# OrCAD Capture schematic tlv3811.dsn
size A
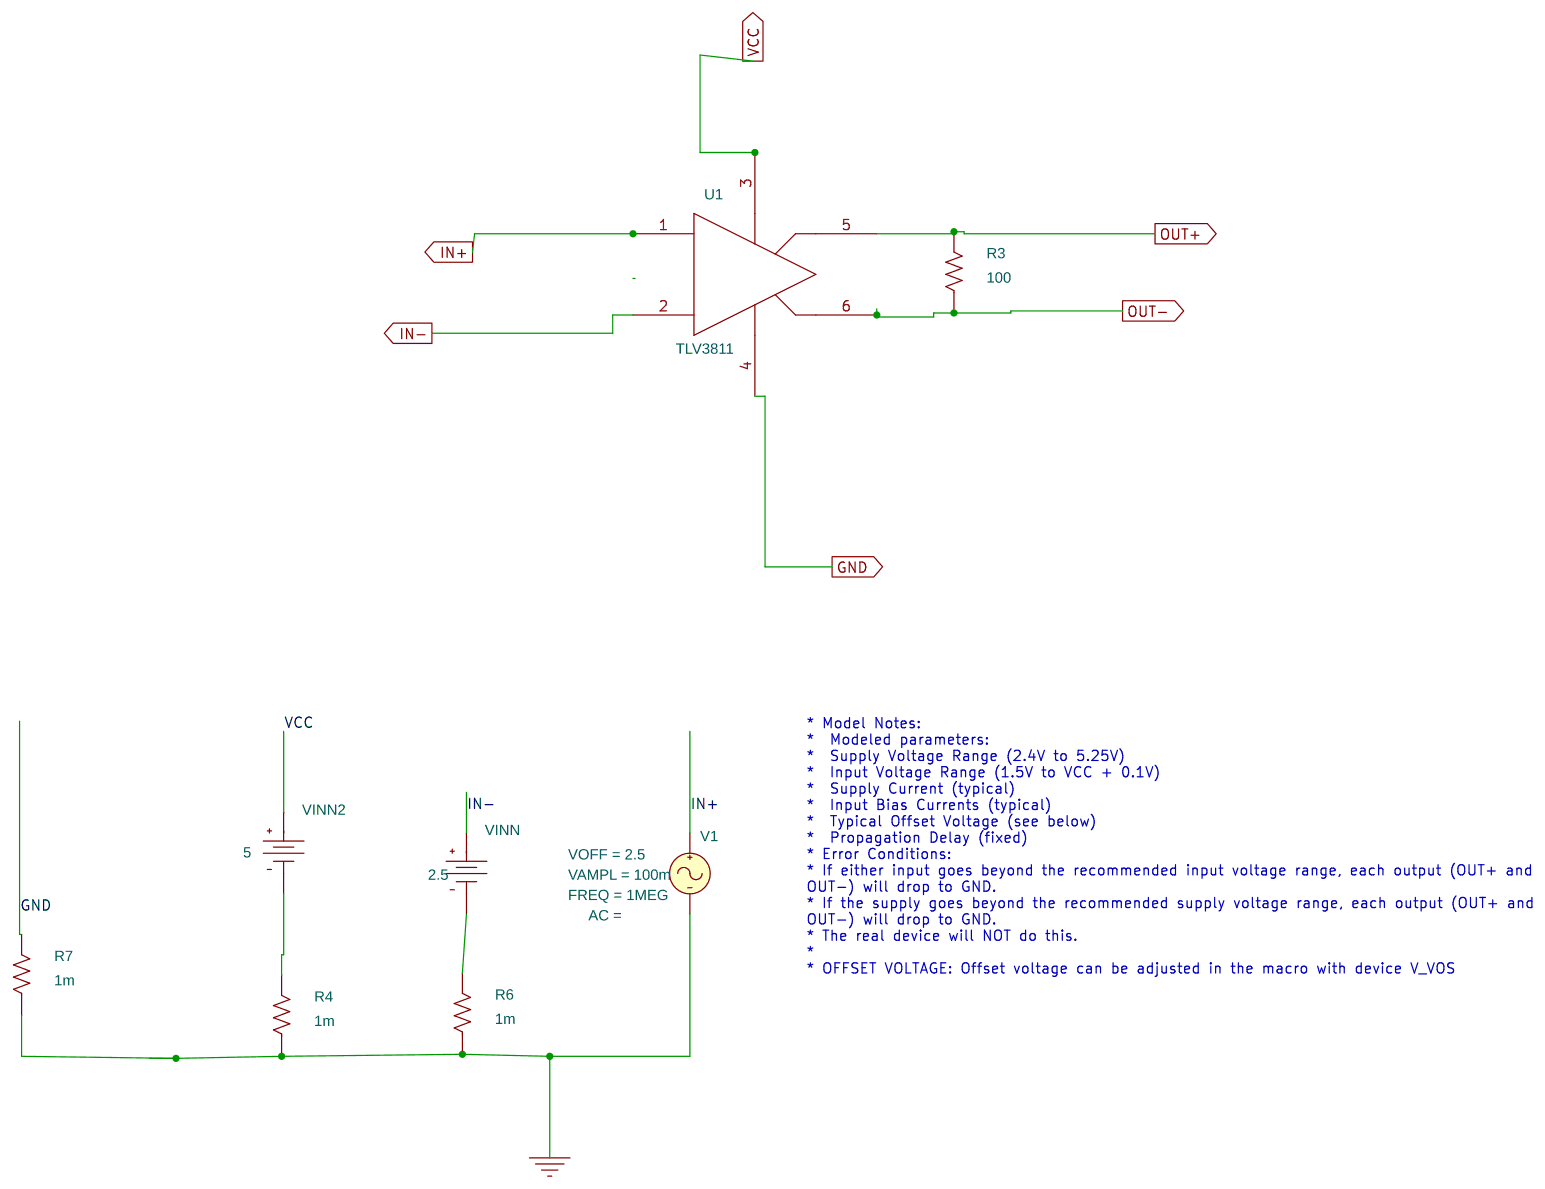
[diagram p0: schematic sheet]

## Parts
R3  100  [AXRC05]
R4  1m  [AXRC05]
R6  1m  [AXRC05]
R7  1m  [AXRC05]
U1  TLV3811
V1  VSIN
VINN  VDC
VINN2  VDC

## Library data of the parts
R3 R4 R6 R7 = R
U1 = TLV3811
V1 = VSIN: FREQ: 1MEG; VAMPL: 100m; VOFF: 2.5
VINN = VDC: DC: 2.5
VINN2 = VDC: DC: 5

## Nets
GND: R7.2 U1.4(GND)
VCC: U1.3(VCC) VINN2.0(+)
0: R4.1 R6.1 R7.1 V1.2(-)
IN+: U1.1(IN+) V1.1(+)
IN-: U1.2(IN-) VINN.0(+)
OUT+: R3.2 U1.5(OUT+)
OUT-: R3.1 U1.6(OUT-)
N858336: R4.2 VINN2.1(-)
N858380: R6.2 VINN.1(-)

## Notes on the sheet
- * Model Notes:
  *  Modeled parameters:
  *  Supply Voltage Range (2.4V to 5.25V)
  *  Input Voltage Range (1.5V to VCC + 0.1V)
  *  Supply Current (typical)
  *  Input Bias Currents (typical)
  *  Typical Offset Voltage (see below)
  *  Propagation Delay (fixed)
  * Error Conditions:
  * If either input goes beyond the recommended input voltage range, each output (OUT+ and
  OUT-) will drop to GND.
  * If the supply goes beyond the recommended supply voltage range, each output (OUT+ and
  OUT-) will drop to GND.
  * The real device will NOT do this.
  *
  * OFFSET VOLTAGE: Offset voltage can be adjusted in the macro with device V_VOS
